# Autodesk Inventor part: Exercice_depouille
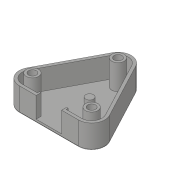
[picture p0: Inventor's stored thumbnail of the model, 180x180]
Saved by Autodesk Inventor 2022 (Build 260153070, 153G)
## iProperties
Created: 2018-06
Part Number: Exercice_depouille
Material: Plastique ABS
Document SubType Name: Modeling
Designer: Fabian Perrée
Density: 1.06 g/cm^3
Appearance: Gris clair
Mass: 7.82351 g
Surface Area: 92.0535 cm^2
Volume: 7.38067 cm^3
Author: Fabian Perrée
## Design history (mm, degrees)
sketch "Esquisse1"
  geometry: L1 (0, 0)-(0, -59.098); L2 (0, 0)-(7.75, 0); L3 (25.07, -11.743)-(7.07, -45.743); L4 (-7.07, -45.743)-(-25.07, -11.743); L5 (-18, 0)-(-7.75, 0); L6 (14.25, -19.25)-(11, -19.25); L7 (9, -21.25)-(14.25, -21.25); L8 (14.25, -21.25)-(14.25, -19.25); L9 (11, -19.25)-(11, -16); L10 (11, -16)-(9, -16); L11 (9, -16)-(9, -21.25); L12 (-23.524, -10.924)-(-5.524, -44.924); L13 (5.524, -44.924)-(23.524, -10.924); L14 (7.75, 0)-(7.75, -3); L15 (7.75, -3)-(8.75, -3); L16 (8.75, -3)-(8.75, -1.75); L17 (-7.75, -3)-(-8.75, -3); L18 (-8.75, -3)-(-8.75, -1.75); L19 (-7.75, 0)-(-7.75, -3); L20 (18, -1.75)-(8.75, -1.75); L21 (-8.75, -1.75)-(-18, -1.75); L22 (7.75, 0)-(18, 0); L23 (-7.75, 0)-(0, 0); C1 r 2.375 at (18, -8); C2 r 2.375 at (-18, -8); C3 r 2.375 at (0, -42); C4 r 3.75 at (18, -8); C5 r 3.75 at (0, -42); C6 r 3.75 at (-18, -8); C7 r 2.375 at (0, -24.75); A1 r 8 centre (18, -8) between (25.07, -11.743) and (18, 0); A2 r 8 centre (0, -42) between (-7.07, -45.743) and (7.07, -45.743); A3 r 8 centre (-18, -8) between (-18, 0) and (-25.07, -11.743); A4 r 6.25 centre (-18, -8) between (-18, -1.75) and (-23.524, -10.924); A5 r 6.25 centre (0, -42) between (-5.524, -44.924) and (5.524, -44.924); A6 r 6.25 centre (18, -8) between (23.524, -10.924) and (18, -1.75); 1 further point
  constraints: 46 end point, 13 centre point, 12 point on circle, 10 tangent, 8 perpendicular, 7 point on line, 6 equal radius, 4 horizontal, 4 symmetric about line, 3 coincident, 3 vertical, 2 concentric, 1 parallel, 6 other
  dimensions: "d0" = 34 vertical distance of C3.centre C1.centre; "d1" = 2 distance of L7.end L6.start; "d2" = 3.25 distance of L6.end L9.end; "d3" = 9 distance between parallel lines of L1 L11; "d4" = 13.25 distance from line of C1.centre L7; "d5" = 8 radius of A1; "d6" = 7.5 diameter of C4; "d7" = 36 distance of C2.centre C1.centre; "d8" = 4.75 diameter of C1; "d9" = 4.75 diameter of C7; "d10" = 16.75 vertical distance of C1.centre C7.centre; "d11" = 1.75 radial gap between concentric circles of A1 A6; "d12" = 1 distance of L14.end L15.end; "d13" = 15.5 diameter of L14 L1; "d14" = 3 distance of L2.end L14.end; "d41" = 5.25 distance of L10.end L7.start
extrude "Extrusion1" new body sketch "Esquisse1" distance "d15" = 1.75; taper "d16" = 0 deg
extrude "Extrusion2" join sketch "Esquisse1" distance "d17" = 12.5; taper "d18" = 0 deg
extrude "Extrusion3" join sketch "Esquisse1" distance "d19" = 15.25; taper "d20" = 0 deg
extrude "Extrusion4" join sketch "Esquisse1" distance "d21" = 3.25; taper "d22" = 0 deg
node "Plan de construction1"
fillet "Congé1" dims "d40" = 0.5
node "Solide1"
other parameters: "d23" = 3.25
